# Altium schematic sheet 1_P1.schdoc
size 307 x 218 mm; Symbol: Drawing-Symbol_A4; Device: Drawing-Symbol_A4; @Project Name: Sivasankar's Hackpad00001; @Page Count: 1; @Update Date: 2026-02-22; @Create Date: 2026-02-22; @Schematic Name: Schematic1_1; @Page No: 1; @Page Name: P1; Company: EasyEDA.com; Version: V1.0; Page Size: A4; @Create Time: 08:34:42; @Update Time: 14:04:43; Width: 1170; Height: 825; Region Start: 1; X Region Count: 6; Y Region Count: 4; Blade Width: 10; Title Block Position: 3; @Board Name: Board1_1
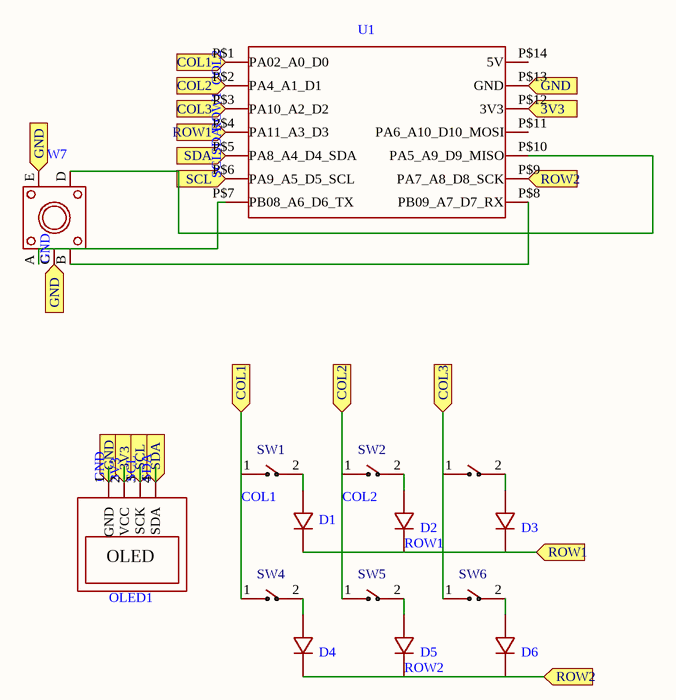
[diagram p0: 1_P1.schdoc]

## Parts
D1  1N4148  [DO-35_BD2.0-L4.0-P8.00-D0.5-FD]  (value not drawn)
D2  1N4148  [DO-35_BD2.0-L4.0-P8.00-D0.5-FD]  (value not drawn)
D3  1N4148  [DO-35_BD2.0-L4.0-P8.00-D0.5-FD]  (value not drawn)
D4  1N4148  [DO-35_BD2.0-L4.0-P8.00-D0.5-FD]  (value not drawn)
D5  1N4148  [DO-35_BD2.0-L4.0-P8.00-D0.5-FD]  (value not drawn)
D6  1N4148  [DO-35_BD2.0-L4.0-P8.00-D0.5-FD]  (value not drawn)
OLED1  OLED 0.91  [I2C OLED 0.91]  (value not drawn)
SW1  MX1A-E1NW  [SW-TH_MX1A-E1NW]  (value not drawn)
SW2  MX1A-E1NW  [SW-TH_MX1A-E1NW]  (value not drawn)
SW3  MX1A-E1NW  [SW-TH_MX1A-E1NW]  (value not drawn)
SW4  MX1A-E1NW  [SW-TH_MX1A-E1NW]  (value not drawn)
SW5  MX1A-E1NW  [SW-TH_MX1A-E1NW]  (value not drawn)
SW6  MX1A-E1NW  [SW-TH_MX1A-E1NW]  (value not drawn)
SW7  EC11  [SW-TH_EC111XXXX]  (value not drawn)
U1  XIAO_RP2040_XIAO_RP2040_THROUGH_HOLE  [XIAO_THROUGH_HOLE]  (value not drawn)

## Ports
3V3 (in), COL1 (in), COL2 (in), COL3 (in), GND (in), ROW1 (in), ROW2 (in), SCL (in), SDA (in)

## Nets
3V3: OLED1.2(VCC) U1.P$12(3V3) ; port 3V3
COL1: SW1.1 SW4.1 U1.P$1(PA02_A0_D0) ; port COL1
COL2: SW2.1 SW5.1 U1.P$2(PA4_A1_D1) ; port COL2
COL3: SW3.1 SW6.1 U1.P$3(PA10_A2_D2) ; port COL3
GND: OLED1.1(GND) SW7.C SW7.E U1.P$13(GND) ; port GND
ROW1: D1.2(K) D2.2(K) D3.2(K) U1.P$4(PA11_A3_D3) ; port ROW1
ROW2: D4.2(K) D5.2(K) D6.2(K) U1.P$9(PA7_A8_D8_SCK) ; port ROW2
SCL: OLED1.3(SCK) U1.P$6(PA9_A5_D5_SCL) ; port SCL
SDA: OLED1.4(SDA) U1.P$5(PA8_A4_D4_SDA) ; port SDA
NetD1_1: D1.1(A) SW1.2
NetD2_1: D2.1(A) SW2.2
NetD3_1: D3.1(A) SW3.2
NetD4_1: D4.1(A) SW4.2
NetD5_1: D5.1(A) SW5.2
NetD6_1: D6.1(A) SW6.2
NetSW7_A: SW7.A U1.P$7(PB08_A6_D6_TX)
NetSW7_B: SW7.B U1.P$8(PB09_A7_D7_RX)
NetSW7_D: SW7.D U1.P$10(PA5_A9_D9_MISO)

Not connected (* = marked no-connect by the designer): U1 P$11(PA6_A10_D10_MOSI) P$14(5V)

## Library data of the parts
D1-D6 = 1N4148_C258182: Manufacturer: onsemi(安森美); Add into BOM: yes; Forward Voltage (Vf@If): 1V@10mA; Reverse Leakage Current: 5uA@75V
OLED1 = OLED 0.91: Manufacturer Part: SSD1306 I2C OLED; Add into BOM: yes
SW1-SW6 = MX1A-E1NW: Manufacturer: CHERRY; Add into BOM: yes
SW7 = EC11: Manufacturer: ALPS Electric; Manufacturer Part: EC1110120005; Add into BOM: yes
U1 = XIAO_RP2040_XIAO_RP2040_THROUGH_HOLE: Add into BOM: yes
